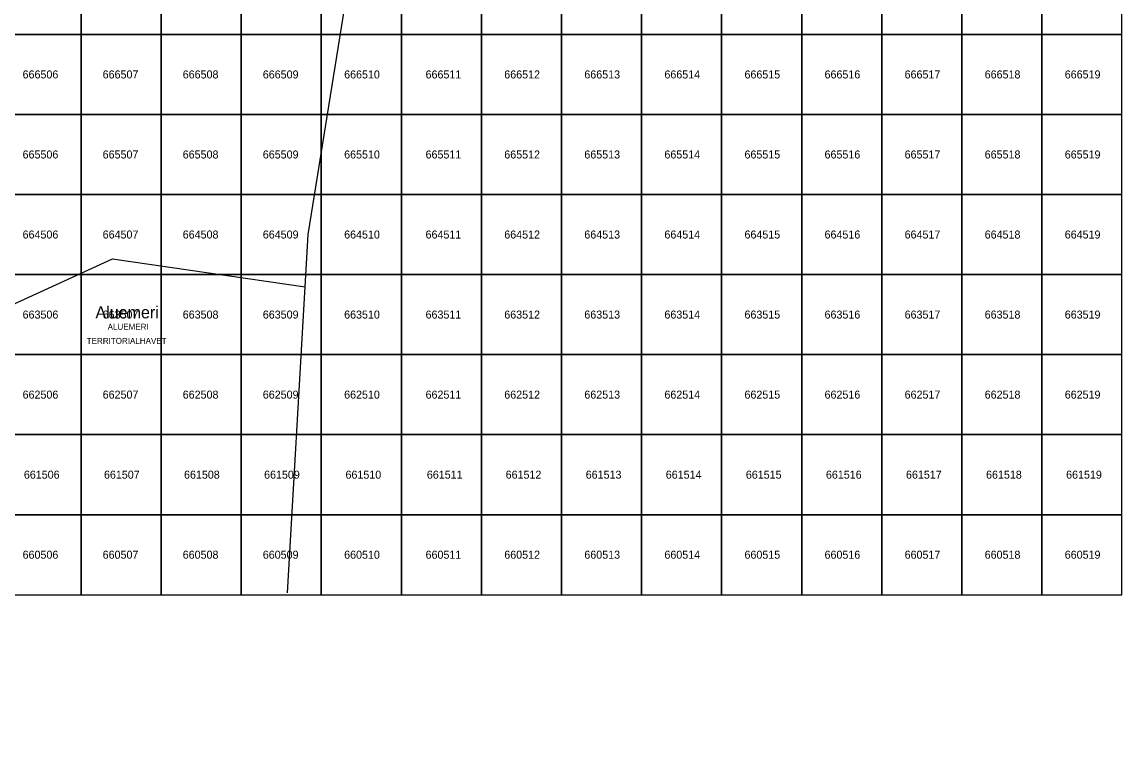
# Model space of a CAD drawing. Extents: x 25485000 to 25520000, y 6656775 to 6690000.
# Drawn here: x 25506262 to 25520000, y 6658048 to 6667155 of the extents above; entities that cross this region are included whole.
import ezdxf

# ---------------------------------------------------------------- set-up
doc = ezdxf.new("R2010")
doc.units = 0
doc.layers.add('Level 63', color=7, linetype='Continuous')

msp = doc.modelspace()

# ---------------------------------------------------------------- linework, layer by layer
at = {"layer": 'Level 63'}
for points in [[(25493980, 6658048), (25507391, 6664195), (25509799, 6663845), (25509837, 6664502), (25510789, 6670428), (25511000, 6671303), (25512177, 6676150), (25511162, 6676439), (25510000, 6674363), (25509223, 6672976), (25508913, 6672423), (25508747, 6672531), (25508848, 6671851), (25508934, 6671264), (25508231, 6671039), (25506885, 6670907), (25506884, 6670120), (25506882, 6668503), (25506580, 6668434), (25501638, 6667311)], [(25509578, 6660024), (25509799, 6663845)]]:
    msp.add_lwpolyline(points, dxfattribs=at)
for points in [[(25506000, 6667000), (25507000, 6667000), (25507000, 6668000), (25506000, 6668000)], [(25507000, 6667000), (25508000, 6667000), (25508000, 6668000), (25507000, 6668000)], [(25508000, 6667000), (25509000, 6667000), (25509000, 6668000), (25508000, 6668000)], [(25509000, 6667000), (25510000, 6667000), (25510000, 6668000), (25509000, 6668000)], [(25510000, 6667000), (25511000, 6667000), (25511000, 6668000), (25510000, 6668000)], [(25511000, 6667000), (25512000, 6667000), (25512000, 6668000), (25511000, 6668000)], [(25512000, 6667000), (25513000, 6667000), (25513000, 6668000), (25512000, 6668000)], [(25513000, 6667000), (25514000, 6667000), (25514000, 6668000), (25513000, 6668000)], [(25514000, 6667000), (25515000, 6667000), (25515000, 6668000), (25514000, 6668000)], [(25515000, 6667000), (25516000, 6667000), (25516000, 6668000), (25515000, 6668000)], [(25516000, 6667000), (25517000, 6667000), (25517000, 6668000), (25516000, 6668000)], [(25517000, 6667000), (25518000, 6667000), (25518000, 6668000), (25517000, 6668000)], [(25518000, 6667000), (25519000, 6667000), (25519000, 6668000), (25518000, 6668000)], [(25519000, 6667000), (25520000, 6667000), (25520000, 6668000), (25519000, 6668000)], [(25506000, 6666000), (25507000, 6666000), (25507000, 6667000), (25506000, 6667000)], [(25507000, 6666000), (25508000, 6666000), (25508000, 6667000), (25507000, 6667000)], [(25508000, 6666000), (25509000, 6666000), (25509000, 6667000), (25508000, 6667000)], [(25509000, 6666000), (25510000, 6666000), (25510000, 6667000), (25509000, 6667000)], [(25510000, 6666000), (25511000, 6666000), (25511000, 6667000), (25510000, 6667000)], [(25511000, 6666000), (25512000, 6666000), (25512000, 6667000), (25511000, 6667000)], [(25512000, 6666000), (25513000, 6666000), (25513000, 6667000), (25512000, 6667000)], [(25513000, 6666000), (25514000, 6666000), (25514000, 6667000), (25513000, 6667000)], [(25514000, 6666000), (25515000, 6666000), (25515000, 6667000), (25514000, 6667000)], [(25515000, 6666000), (25516000, 6666000), (25516000, 6667000), (25515000, 6667000)], [(25516000, 6666000), (25517000, 6666000), (25517000, 6667000), (25516000, 6667000)], [(25517000, 6666000), (25518000, 6666000), (25518000, 6667000), (25517000, 6667000)], [(25518000, 6666000), (25519000, 6666000), (25519000, 6667000), (25518000, 6667000)], [(25519000, 6666000), (25520000, 6666000), (25520000, 6667000), (25519000, 6667000)], [(25506000, 6665000), (25507000, 6665000), (25507000, 6666000), (25506000, 6666000)], [(25507000, 6665000), (25508000, 6665000), (25508000, 6666000), (25507000, 6666000)], [(25508000, 6665000), (25509000, 6665000), (25509000, 6666000), (25508000, 6666000)], [(25509000, 6665000), (25510000, 6665000), (25510000, 6666000), (25509000, 6666000)], [(25510000, 6665000), (25511000, 6665000), (25511000, 6666000), (25510000, 6666000)], [(25511000, 6665000), (25512000, 6665000), (25512000, 6666000), (25511000, 6666000)], [(25512000, 6665000), (25513000, 6665000), (25513000, 6666000), (25512000, 6666000)], [(25513000, 6665000), (25514000, 6665000), (25514000, 6666000), (25513000, 6666000)], [(25514000, 6665000), (25515000, 6665000), (25515000, 6666000), (25514000, 6666000)], [(25515000, 6665000), (25516000, 6665000), (25516000, 6666000), (25515000, 6666000)], [(25516000, 6665000), (25517000, 6665000), (25517000, 6666000), (25516000, 6666000)], [(25517000, 6665000), (25518000, 6665000), (25518000, 6666000), (25517000, 6666000)], [(25518000, 6665000), (25519000, 6665000), (25519000, 6666000), (25518000, 6666000)], [(25519000, 6665000), (25520000, 6665000), (25520000, 6666000), (25519000, 6666000)], [(25506000, 6664000), (25507000, 6664000), (25507000, 6665000), (25506000, 6665000)], [(25507000, 6664000), (25508000, 6664000), (25508000, 6665000), (25507000, 6665000)], [(25508000, 6664000), (25509000, 6664000), (25509000, 6665000), (25508000, 6665000)], [(25509000, 6664000), (25510000, 6664000), (25510000, 6665000), (25509000, 6665000)], [(25510000, 6664000), (25511000, 6664000), (25511000, 6665000), (25510000, 6665000)], [(25511000, 6664000), (25512000, 6664000), (25512000, 6665000), (25511000, 6665000)], [(25512000, 6664000), (25513000, 6664000), (25513000, 6665000), (25512000, 6665000)], [(25513000, 6664000), (25514000, 6664000), (25514000, 6665000), (25513000, 6665000)], [(25514000, 6664000), (25515000, 6664000), (25515000, 6665000), (25514000, 6665000)], [(25515000, 6664000), (25516000, 6664000), (25516000, 6665000), (25515000, 6665000)], [(25516000, 6664000), (25517000, 6664000), (25517000, 6665000), (25516000, 6665000)], [(25517000, 6664000), (25518000, 6664000), (25518000, 6665000), (25517000, 6665000)], [(25518000, 6664000), (25519000, 6664000), (25519000, 6665000), (25518000, 6665000)], [(25519000, 6664000), (25520000, 6664000), (25520000, 6665000), (25519000, 6665000)], [(25506000, 6663000), (25507000, 6663000), (25507000, 6664000), (25506000, 6664000)], [(25507000, 6663000), (25508000, 6663000), (25508000, 6664000), (25507000, 6664000)], [(25508000, 6663000), (25509000, 6663000), (25509000, 6664000), (25508000, 6664000)], [(25509000, 6663000), (25510000, 6663000), (25510000, 6664000), (25509000, 6664000)], [(25510000, 6663000), (25511000, 6663000), (25511000, 6664000), (25510000, 6664000)], [(25511000, 6663000), (25512000, 6663000), (25512000, 6664000), (25511000, 6664000)], [(25512000, 6663000), (25513000, 6663000), (25513000, 6664000), (25512000, 6664000)], [(25513000, 6663000), (25514000, 6663000), (25514000, 6664000), (25513000, 6664000)], [(25514000, 6663000), (25515000, 6663000), (25515000, 6664000), (25514000, 6664000)], [(25515000, 6663000), (25516000, 6663000), (25516000, 6664000), (25515000, 6664000)], [(25516000, 6663000), (25517000, 6663000), (25517000, 6664000), (25516000, 6664000)], [(25517000, 6663000), (25518000, 6663000), (25518000, 6664000), (25517000, 6664000)], [(25518000, 6663000), (25519000, 6663000), (25519000, 6664000), (25518000, 6664000)], [(25519000, 6663000), (25520000, 6663000), (25520000, 6664000), (25519000, 6664000)], [(25506000, 6662000), (25507000, 6662000), (25507000, 6663000), (25506000, 6663000)], [(25507000, 6662000), (25508000, 6662000), (25508000, 6663000), (25507000, 6663000)], [(25508000, 6662000), (25509000, 6662000), (25509000, 6663000), (25508000, 6663000)], [(25509000, 6662000), (25510000, 6662000), (25510000, 6663000), (25509000, 6663000)], [(25510000, 6662000), (25511000, 6662000), (25511000, 6663000), (25510000, 6663000)], [(25511000, 6662000), (25512000, 6662000), (25512000, 6663000), (25511000, 6663000)], [(25512000, 6662000), (25513000, 6662000), (25513000, 6663000), (25512000, 6663000)], [(25513000, 6662000), (25514000, 6662000), (25514000, 6663000), (25513000, 6663000)], [(25514000, 6662000), (25515000, 6662000), (25515000, 6663000), (25514000, 6663000)], [(25515000, 6662000), (25516000, 6662000), (25516000, 6663000), (25515000, 6663000)], [(25516000, 6662000), (25517000, 6662000), (25517000, 6663000), (25516000, 6663000)], [(25517000, 6662000), (25518000, 6662000), (25518000, 6663000), (25517000, 6663000)], [(25518000, 6662000), (25519000, 6662000), (25519000, 6663000), (25518000, 6663000)], [(25519000, 6662000), (25520000, 6662000), (25520000, 6663000), (25519000, 6663000)], [(25506000, 6661000), (25507000, 6661000), (25507000, 6662000), (25506000, 6662000)], [(25507000, 6661000), (25508000, 6661000), (25508000, 6662000), (25507000, 6662000)], [(25508000, 6661000), (25509000, 6661000), (25509000, 6662000), (25508000, 6662000)], [(25509000, 6661000), (25510000, 6661000), (25510000, 6662000), (25509000, 6662000)], [(25510000, 6661000), (25511000, 6661000), (25511000, 6662000), (25510000, 6662000)], [(25511000, 6661000), (25512000, 6661000), (25512000, 6662000), (25511000, 6662000)], [(25512000, 6661000), (25513000, 6661000), (25513000, 6662000), (25512000, 6662000)], [(25513000, 6661000), (25514000, 6661000), (25514000, 6662000), (25513000, 6662000)], [(25514000, 6661000), (25515000, 6661000), (25515000, 6662000), (25514000, 6662000)], [(25515000, 6661000), (25516000, 6661000), (25516000, 6662000), (25515000, 6662000)], [(25516000, 6661000), (25517000, 6661000), (25517000, 6662000), (25516000, 6662000)], [(25517000, 6661000), (25518000, 6661000), (25518000, 6662000), (25517000, 6662000)], [(25518000, 6661000), (25519000, 6661000), (25519000, 6662000), (25518000, 6662000)], [(25519000, 6661000), (25520000, 6661000), (25520000, 6662000), (25519000, 6662000)], [(25506000, 6660000), (25507000, 6660000), (25507000, 6661000), (25506000, 6661000)], [(25507000, 6660000), (25508000, 6660000), (25508000, 6661000), (25507000, 6661000)], [(25508000, 6660000), (25509000, 6660000), (25509000, 6661000), (25508000, 6661000)], [(25509000, 6660000), (25510000, 6660000), (25510000, 6661000), (25509000, 6661000)], [(25510000, 6660000), (25511000, 6660000), (25511000, 6661000), (25510000, 6661000)], [(25511000, 6660000), (25512000, 6660000), (25512000, 6661000), (25511000, 6661000)], [(25512000, 6660000), (25513000, 6660000), (25513000, 6661000), (25512000, 6661000)], [(25513000, 6660000), (25514000, 6660000), (25514000, 6661000), (25513000, 6661000)], [(25514000, 6660000), (25515000, 6660000), (25515000, 6661000), (25514000, 6661000)], [(25515000, 6660000), (25516000, 6660000), (25516000, 6661000), (25515000, 6661000)], [(25516000, 6660000), (25517000, 6660000), (25517000, 6661000), (25516000, 6661000)], [(25517000, 6660000), (25518000, 6660000), (25518000, 6661000), (25517000, 6661000)], [(25518000, 6660000), (25519000, 6660000), (25519000, 6661000), (25518000, 6661000)], [(25519000, 6660000), (25520000, 6660000), (25520000, 6661000), (25519000, 6661000)]]:
    msp.add_lwpolyline(points, close=True, dxfattribs=at)

# ---------------------------------------------------------------- texts
for s, height, p in [('666506', 100, (25506269, 6666450)), ('666507', 100, (25507269, 6666450)), ('666508', 100, (25508269, 6666450)), ('666509', 100, (25509269, 6666450)), ('666510', 100, (25510285, 6666450)), ('666511', 100, (25511302, 6666450)), ('666512', 100, (25512285, 6666450)), ('666513', 100, (25513285, 6666450)), ('666514', 100, (25514285, 6666450)), ('666515', 100, (25515285, 6666450)), ('666516', 100, (25516285, 6666450)), ('666517', 100, (25517285, 6666450)), ('666518', 100, (25518285, 6666450)), ('666519', 100, (25519285, 6666450)), ('665506', 100, (25506269, 6665450)), ('665507', 100, (25507269, 6665450)), ('665508', 100, (25508269, 6665450)), ('665509', 100, (25509269, 6665450)), ('665510', 100, (25510285, 6665450)), ('665511', 100, (25511302, 6665450)), ('665512', 100, (25512285, 6665450)), ('665513', 100, (25513285, 6665450)), ('665514', 100, (25514285, 6665450)), ('665515', 100, (25515285, 6665450)), ('665516', 100, (25516285, 6665450)), ('665517', 100, (25517285, 6665450)), ('665518', 100, (25518285, 6665450)), ('665519', 100, (25519285, 6665450)), ('664506', 100, (25506269, 6664450)), ('664507', 100, (25507269, 6664450)), ('664508', 100, (25508269, 6664450)), ('664509', 100, (25509269, 6664450)), ('664510', 100, (25510285, 6664450)), ('664511', 100, (25511302, 6664450)), ('664512', 100, (25512285, 6664450)), ('664513', 100, (25513285, 6664450)), ('664514', 100, (25514285, 6664450)), ('664515', 100, (25515285, 6664450)), ('664516', 100, (25516285, 6664450)), ('664517', 100, (25517285, 6664450)), ('664518', 100, (25518285, 6664450)), ('664519', 100, (25519285, 6664450)), ('Aluemeri', 150, (25507179, 6663453)), ('663506', 100, (25506269, 6663450)), ('663507', 100, (25507269, 6663450)), ('663508', 100, (25508269, 6663450)), ('663509', 100, (25509269, 6663450)), ('663510', 100, (25510285, 6663450)), ('663511', 100, (25511302, 6663450)), ('663512', 100, (25512285, 6663450)), ('663513', 100, (25513285, 6663450)), ('663514', 100, (25514285, 6663450)), ('663515', 100, (25515285, 6663450)), ('663516', 100, (25516285, 6663450)), ('663517', 100, (25517285, 6663450)), ('663518', 100, (25518285, 6663450)), ('663519', 100, (25519285, 6663450)), ('ALUEMERI', 75, (25507331, 6663310)), ('TERRITORIALHAVET', 75, (25507070, 6663134)), ('662506', 100, (25506269, 6662450)), ('662507', 100, (25507269, 6662450)), ('662508', 100, (25508269, 6662450)), ('662509', 100, (25509269, 6662450)), ('662510', 100, (25510285, 6662450)), ('662511', 100, (25511302, 6662450)), ('662512', 100, (25512285, 6662450)), ('662513', 100, (25513285, 6662450)), ('662514', 100, (25514285, 6662450)), ('662515', 100, (25515285, 6662450)), ('662516', 100, (25516285, 6662450)), ('662517', 100, (25517285, 6662450)), ('662518', 100, (25518285, 6662450)), ('662519', 100, (25519285, 6662450)), ('661506', 100, (25506285, 6661450)), ('661507', 100, (25507285, 6661450)), ('661508', 100, (25508285, 6661450)), ('661509', 100, (25509285, 6661450)), ('661510', 100, (25510302, 6661450)), ('661511', 100, (25511318, 6661450)), ('661512', 100, (25512302, 6661450)), ('661513', 100, (25513302, 6661450)), ('661514', 100, (25514302, 6661450)), ('661515', 100, (25515302, 6661450)), ('661516', 100, (25516302, 6661450)), ('661517', 100, (25517302, 6661450)), ('661518', 100, (25518302, 6661450)), ('661519', 100, (25519302, 6661450)), ('660506', 100, (25506269, 6660450)), ('660507', 100, (25507269, 6660450)), ('660508', 100, (25508269, 6660450)), ('660509', 100, (25509269, 6660450)), ('660510', 100, (25510285, 6660450)), ('660511', 100, (25511302, 6660450)), ('660512', 100, (25512285, 6660450)), ('660513', 100, (25513285, 6660450)), ('660514', 100, (25514285, 6660450)), ('660515', 100, (25515285, 6660450)), ('660516', 100, (25516285, 6660450)), ('660517', 100, (25517285, 6660450)), ('660518', 100, (25518285, 6660450)), ('660519', 100, (25519285, 6660450))]:
    msp.add_text(s, height=height, dxfattribs=at).set_placement(p)

doc.saveas('drawing.dxf')
